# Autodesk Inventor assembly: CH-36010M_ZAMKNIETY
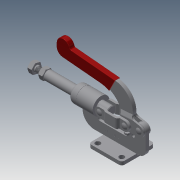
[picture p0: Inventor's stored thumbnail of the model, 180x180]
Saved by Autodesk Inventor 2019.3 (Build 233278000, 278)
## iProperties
Company: Î¢ÈíÖÐ¹ú
Created: 2012-09
Part Number: CH-36010M_ZAMKNIETY
Material: Ogólny
Description: STEP AP203
Document SubType Name: Assembly
Designer: CADENGINEERING4
Sending System: SolidWorks 2010
Preprocessor: SwSTEP 2.0
Title: CH-36010M.STEP
Author: Î¢ÈíÓÃ»§
Revision Number: ÈÎºÎ
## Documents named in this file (14)
- D:\Vault_2016\Projekty\STRONA\Push-pull clamp\CH-36010M\CH-36010M_ZAMKNIETY.iam
- D:\Vault_2016\Projekty\STRONA\Push-pull clamp\CH-36010M\CH-36010M-01 BASE.ipt
- D:\Vault_2016\Projekty\STRONA\Push-pull clamp\CH-36010M\CH-36010M-06.ipt
- D:\Vault_2016\Projekty\STRONA\Push-pull clamp\CH-36010M\CH-36010M-05 LEAD SET.ipt
- D:\Vault_2016\Projekty\STRONA\Push-pull clamp\CH-36010M\CH-36010M-04 CONNECTING-PLATE.ipt
- D:\Vault_2016\Projekty\STRONA\Push-pull clamp\CH-36010M\CH-36010M-08.ipt
- D:\Vault_2016\Projekty\STRONA\Push-pull clamp\CH-36010M\CH-36010M-09.ipt
- D:\Vault_2016\Projekty\STRONA\Push-pull clamp\CH-36010M\CH-36010M-10.ipt
- D:\Vault_2016\Projekty\STRONA\Push-pull clamp\CH-36010M\M10 Nut.ipt
- D:\Vault_2016\Projekty\STRONA\Push-pull clamp\CH-36010M\CH-36010M-02 CREST STALK.ipt
- D:\Vault_2016\Projekty\STRONA\Push-pull clamp\CH-36010M\CH-36010M-07.ipt
- D:\Vault_2016\Projekty\STRONA\Push-pull clamp\CH-36010M\CH-36010M-11.ipt
- D:\Vault_2016\Projekty\STRONA\Push-pull clamp\CH-36010M\CH-36010M-03 HANDLE.ipt
- D:\Vault_2016\Projekty\STRONA\Push-pull clamp\CH-36010M\CH-SA-105015 SPINDLE SUPPLIED.ipt
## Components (14 placed, 14 different names)
1. CH-36010M-01 BASE_1
2. CH-36010M-06_2
3. CH-36010M-05 LEAD SET_3
4. CH-36010M-04 CONNECTING-PLATE_4
5. CH-36010M-08_5
6. CH-36010M-09_6
7. CH-36010M-10_7
8. M10 Nut_8
9. CH-36010M-02 CREST STALK_9
10. CH-36010M-07_10
11. CH-36010M-04 CONNECTING-PLATE_11
12. CH-36010M-11_12
13. CH-36010M-03 HANDLE_13
14. CH-SA-105015 SPINDLE SUPPLIED_14
